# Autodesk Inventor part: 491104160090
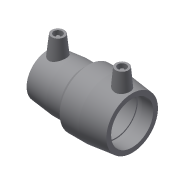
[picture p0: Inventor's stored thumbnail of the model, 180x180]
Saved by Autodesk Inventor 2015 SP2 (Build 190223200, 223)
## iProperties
Created: 2017-06
Part Number: 491104160090
Material: Generic
Description: PLASSON REDUCING COUPLER 160-90
Document SubType Name: Modeling
Designer: KIM
Mass: 54.8237 g
Surface Area: 155.252 cm^2
Volume: 54.8237 cm^3
Density: 1 g/cm^3
Appearance: Default
Author: KIM
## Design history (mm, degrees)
derived "491104.ipt"
feature "Solid1::491104.ipt"
tag "TaggingFeature1"
body "Solid1"
other parameters: "d0" = 193, "d2" = 116, "d3" = 72, "d4" = 43.2, "d5" = 104.4, "d8" = 168 deg, "d10" = 28.8, "d11" = 9.6, "d13" = 193, "d14" = 17.6296, "d15" = 72, "d19" = 3.6, "d20" = 168 deg, "d22" = 108.92847, "d25" = 135 deg, "d29" = 69, "d30" = 15, "d31" = 67.55, "d34" = 6 deg, "d35" = 15, "d38" = 19.5, "d39" = 5 deg, "d41" = 4, "d42" = 14, "d43" = 0, "d45" = 4, "d46" = 14, "d47" = 0, "d48" = 116, "d50" = 199, "d52" = 81, "d53" = 37.6, "d54" = 12.53333, "d55" = 168 deg, "d56" = 56.4, "d57" = 94, "d58" = 179.1, "d59" = 3.6, "d60" = 135 deg, "d61" = 105, "d62" = 15, "d64" = 4, "d66" = 5 deg, "d67" = 14, "d68" = 0, "d69" = 67.55, "d70" = 116, "d71" = 199, "d73" = 187.06, "d76" = 3.6, "d77" = 168 deg, "d79" = 3.6, "d80" = 94, "d81" = 81, "d82" = 109.04, "d83" = 120 deg, "d88" = 15, "d89" = 17, "d90" = 5 deg, "d92" = 4, "d93" = 14, "d94" = 0, "d95" = 3, "d96" = 0, "d97" = 3, "d98" = 0, "d99" = 20.88, "d100" = 5.22, "d101" = 105.7688, "d102" = 20 deg, "d103" = 27.26, "d104" = 6.815, "d105" = 181.4482, "d106" = 3.60705, "d107" = 3, "d108" = 0, "d109" = 3, "d110" = 0, "L_" = 193, "L_2" = 72, "D_1" = 116, "A_1" = 69, "d_2" = 12, "L_1" = 94, "A_" = 105, "D_" = 199
